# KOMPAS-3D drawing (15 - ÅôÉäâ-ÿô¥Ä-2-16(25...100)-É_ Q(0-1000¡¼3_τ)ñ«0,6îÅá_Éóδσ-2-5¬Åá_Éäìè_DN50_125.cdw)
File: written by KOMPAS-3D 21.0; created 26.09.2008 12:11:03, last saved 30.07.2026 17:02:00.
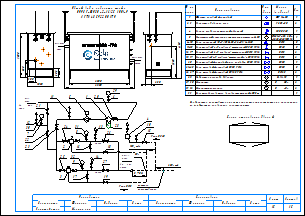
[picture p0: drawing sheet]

Sheets 1-2: A3, landscape

Document properties: Наименование: Макро:21; Автор: RaskoAdmin; Форматы листов документа: 2xA3; Полное имя файла: \\UR38nt01\Departments\КТО\КБ ПУРДГ\Заявки\Прайс-лист на типовые шкафы ГРПШ\ПУРДГ_стандарт_30_04_2026\ПУРДГ с РДНК\ПУРДГ-ШУЭО-2-16(25...100)-Р_ Q(0-1000нм3_ч)до0,6МПа_Рвых-2-5кПа_РДНК_DN50_125.cdw

Title block, sheet 1: Наименование: Пункт учета газа / ПУГ-Ш-400-Р / ЛГТИ.485922.001ТУ; designation: ЛГТИ.03.4411141; sheet number: 1; Количество листов документа: 2; organisation: ООО "ЭЛЬСТЕР Газэлектроника"; Форматы листов документа: A3; stored path: C:\Рабочие документы\Компас\ПУГ\Схема.cdw; Разработал: Устинов; Проверил: Кошкин; Утвердил: Кошкин
Title block, sheet 2: sheet number: 2; stored path: D:\Рабочие документы\Заявки\ПУРДГ\ПУРДГ-ШУЭО-2-100-Р 4411220.cdw; designation, second copy: ЛГТИ.03.4411141-

Views: Вид 1, Вид 2
Referenced files: wcvoit.frw
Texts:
  Normal
  № на
  схеме
  Усл.
  обозн.
  Марка
  (модель)
  Кол.
  Фильтр газовый фланцевый
  ФГ 16-50
  Регулятор давления газа
  РДНК-50
  Клапан предохранительный сбросной
  КПС DN20
  Измерительный комплекс с ротационным счетчиком Ду50
  СГ-ЭК-Р-(0,2...2,0)-
  Кран кнопочный VE-РАСКО-НЗ-1,6-G1/2-М20
  DN15
  Кран шаровой "под приварку" штуцерный DN20 PN16
  DN20
  Кран шаровой "под приварку" штуцерный DN15 PN16
  Кран шаровой "под приварку" штуцерный п/п DN15 PN16
  Кран шаровой фланцевый с мех. приводом DN50 PN16
  Кран шаровой фланцевый DN50 PN16
  Кран шаровой фланцевый DN125 PN16
  DN50
  DN125
  Индикатор перепада давления
  Манометр
  Манометр-напоромер
  Электрообогреватель взрывозащищенный 400Вт
  Delta 15
  0...     МПа
  0...     кПа
  Общий вид и габариты шкафа
  ПУРДГ-ШУЭО-2-16(25...100)-Р
  Выход газа
  Вход газа
  logo-rasko-ge.png
  DN 1
  местное
  сопротивление
  Римп DN15
  Римп DN20
  Выход
  газа
  Р=     кПа
  Вход
  Р=       МПа
  PDI
  Схема открывания дверей
  Предприятие изготовитель может заменять комплектующие на аналогичные,
  не ухудшающие заявленных характеристик.
  Должность
  Конструктор
  Фамилия
  Подпись
  Дата
  Согласовано
  Максимкин
  Лист
  Листов
  POLYLINE_STYLE_0.18_RGB_0_0_0
  POLYLINE_STYLE_0.50_RGB_0_0_0
  POLYLINE_STYLE_0.34_RGB_0_0_0
  PHANTOM_RGB_0_0_0_SC_1_THICK_0.18
  K5LT_THIN_RGB_0_0_0_THICK_0.18
  K5LT32769_RGB_0_0_0_THICK_0.18
  K5LT12_RGB_0_0_0_SC_1_THICK_0.18
  K5LT_DASHED_RGB_0_0_0_SC_1_THICK_0.18
  ACISOTGL_RGB_0_0_0_SC_0.8_THICK_0.25
  CONTINUOUS_RGB_0_127_31_THICK_0.3
  CONTINUOUS_RGB_0_0_255_THICK_0.35
  CONTINUOUS_RGB_255_0_0_THICK_0.35
  POLYLINE_STYLE_0.25_RGB_0_0_0
  CONTINUOUS_RGB_0_0_0_THICK_0.5
  POLYLINE_STYLE_0.35_RGB_0_0_255
  CONTINUOUS_RGB_0_0_0_THICK_0.4
  CONTINUOUS_RGB_0_0_0_THICK_0.35
  НЕВИДИМАЯ_RGB_0_0_0_SC_0.3_THICK_0.25
  СONTINUOUS_RGB_0_0_0_THICK_0.25
  ОСЕВАЯ2_RGB_248_153_30_SC_0.3_THICK_0.25
  Без оформления
Dimensions and other numbers on the sheet: 1; 2, 3; 2; 4; 5; 6-10; 11-15; 16, 17; 18, 19; 20; 21-25; 26, 27; 28; 29, 30; 31, 32; 33; 1500; 250; 300; 1050; 550; 305; 2500; 4130; 2000; 2800; 5,,,7DN 1; 7; 30; 12; 21; 22; 23; 11; 6; 29; 24; 31; 8; 16; 13; 26; 18; 10; 15; 25; 32; 9; 3; 17; 14; 27; 19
